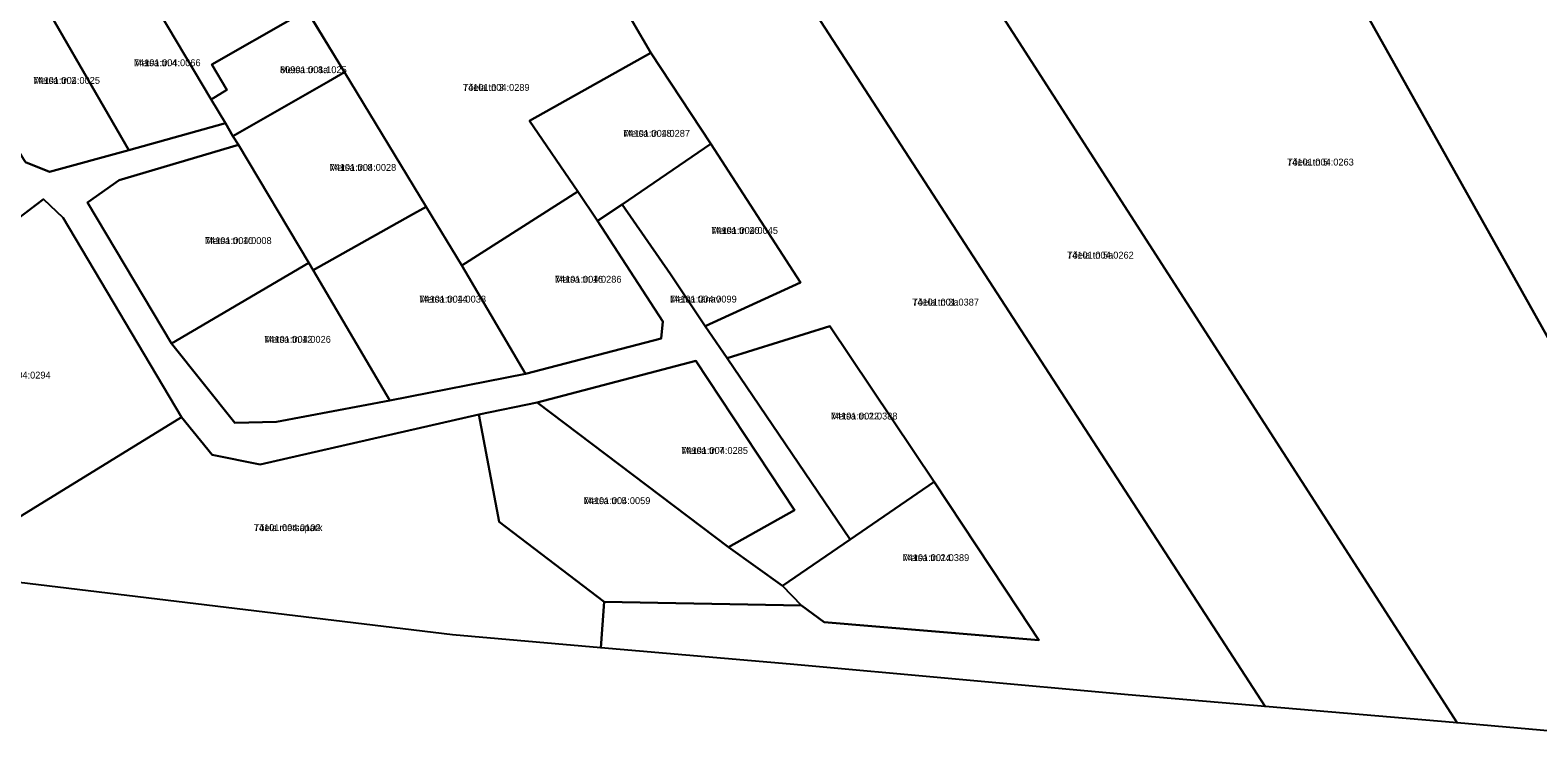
# Model space of a CAD drawing. Extents: x 524000 to 564260, y 6469338 to 6496391.
# Drawn here: x 537928.9 to 538256.7, y 6472778 to 6472932.3 of the extents above; entities that cross this region are included whole.
import ezdxf

# ---------------------------------------------------------------- set-up
doc = ezdxf.new("R2010")
doc.units = 0
for name, color, linetype in [('L_AADRESS', 7, 'Continuous'), ('PIIR', 7, 'Continuous'), ('TUNNUS', 7, 'Continuous')]:
    doc.layers.add(name, color=color, linetype=linetype)

msp = doc.modelspace()

# ---------------------------------------------------------------- linework, layer by layer
at = {"layer": 'PIIR'}
for points in [[(538254.62, 6473081.05), (538407.66, 6472852.49), (538381.66, 6472835.41), (538374.77, 6472836.59), (538368.09, 6472824.25), (538395.14, 6472779.98), (538307.73, 6472778.3), (538204.69, 6472962.04), (538224, 6472975.7), (538226.87, 6472970.76), (538255.54, 6472991.23), (538216.33, 6473054.12)], [(538156.34, 6473048.5), (538204.69, 6472962.04), (538307.73, 6472778.3), (538280.97, 6472777.95), (538239.16, 6472781.62), (538096.61, 6473003.26)], [(538096.61, 6473003.26), (538239.16, 6472781.62), (538197.42, 6472785.22), (538069.5, 6472982.51)], [(538063.82, 6472927.37), (538043.92, 6472961.49), (538069.5, 6472982.51), (538197.42, 6472785.22), (538167.63, 6472787.73), (538094.14, 6472794.44), (538052.97, 6472797.96), (538053.69, 6472807.94), (538096.61, 6472807.14), (538101.49, 6472803.54), (538148.19, 6472799.6), (538143.82, 6472806.23), (538125.46, 6472834.03), (538102.73, 6472867.87), (538080.43, 6472860.92), (538075.66, 6472867.92), (538096.35, 6472877.38), (538076.89, 6472907.52)], [(538022.72, 6472881.08), (538014.96, 6472893.88), (537997.23, 6472923.11), (537982.1, 6472947.96), (538043.92, 6472961.49), (538063.82, 6472927.37), (538037.41, 6472912.57), (538047.97, 6472897.18)], [(537968.23, 6472917.21), (537953.06, 6472942.7), (537977.91, 6472947.2), (537982.1, 6472947.96), (537989.01, 6472936.61), (537986.38, 6472935.11), (537968.34, 6472924.82), (537971.65, 6472919.27)], [(537950.29, 6472906.18), (537931.53, 6472938.68), (537953.06, 6472942.7), (537968.23, 6472917.21), (537971.31, 6472912.04)], [(537927.85, 6472903.53), (537908.79, 6472934.6), (537931.53, 6472938.68), (537950.29, 6472906.18), (537933.05, 6472901.44)], [(537993.74, 6472921.12), (537972.96, 6472909.24), (537971.31, 6472912.04), (537968.23, 6472917.21), (537971.65, 6472919.27), (537968.34, 6472924.82), (537986.38, 6472935.11), (537989.01, 6472936.61), (537997.23, 6472923.11)], [(538047.97, 6472897.18), (538037.41, 6472912.57), (538063.82, 6472927.37), (538076.89, 6472907.52), (538057.56, 6472894.38), (538052.2, 6472890.78)], [(537974.18, 6472907.34), (537972.96, 6472909.24), (537993.74, 6472921.12), (537997.23, 6472923.11), (538014.96, 6472893.88), (538011.59, 6472891.99), (537990.39, 6472880.11), (537989.46, 6472881.7)], [(538076.89, 6472907.52), (538096.35, 6472877.38), (538075.66, 6472867.92), (538068.11, 6472879.2), (538057.56, 6472894.38)], [(537948.25, 6472899.66), (537974.18, 6472907.34), (537989.46, 6472881.7), (537959.58, 6472864.17), (537941.31, 6472894.78)], [(537911.94, 6472817.51), (537880.7, 6472856.63), (537881.69, 6472857.39), (537931.73, 6472895.5), (537936.05, 6472891.43), (537961.8, 6472848.15), (537913.82, 6472818.62)], [(538022.72, 6472881.08), (538047.97, 6472897.18), (538052.2, 6472890.78), (538066.45, 6472868.92), (538066.08, 6472865.25), (538036.57, 6472857.51)], [(537990.39, 6472880.11), (538011.59, 6472891.99), (538014.96, 6472893.88), (538022.72, 6472881.08), (538036.57, 6472857.51), (538007.05, 6472851.75)], [(537973.36, 6472846.89), (537959.58, 6472864.17), (537989.46, 6472881.7), (537990.39, 6472880.11), (538007.05, 6472851.75), (537982.46, 6472847.11)], [(538125.46, 6472834.03), (538107.13, 6472821.5), (538080.43, 6472860.92), (538102.73, 6472867.87)], [(538073.6, 6472860.39), (538095.07, 6472827.89), (538080.71, 6472819.87), (538039.14, 6472851.29)], [(537911.94, 6472817.51), (537913.82, 6472818.62), (537961.8, 6472848.15), (537968.46, 6472839.9), (537978.87, 6472837.81), (538026.41, 6472848.72), (538030.81, 6472825.39), (538053.69, 6472807.94), (538052.97, 6472797.96), (538020.71, 6472800.82), (537915.62, 6472813.49)], [(538026.41, 6472848.72), (538039.14, 6472851.29), (538080.71, 6472819.87), (538092.46, 6472811.47), (538096.61, 6472807.14), (538053.69, 6472807.94), (538030.81, 6472825.39)], [(538096.61, 6472807.14), (538092.46, 6472811.47), (538107.13, 6472821.5), (538125.46, 6472834.03), (538143.82, 6472806.23), (538148.19, 6472799.6), (538101.49, 6472803.54)]]:
    msp.add_lwpolyline(points, close=True, dxfattribs=at)
msp.add_lwpolyline([(537927.85, 6472903.53), (537933.05, 6472901.44), (537950.29, 6472906.18), (537971.31, 6472912.04), (537972.96, 6472909.24), (537974.18, 6472907.34), (537948.25, 6472899.66), (537941.31, 6472894.78), (537959.58, 6472864.17), (537973.36, 6472846.89), (537982.46, 6472847.11), (538007.05, 6472851.75), (538036.57, 6472857.51), (538066.08, 6472865.25), (538066.45, 6472868.92), (538052.2, 6472890.78), (538057.56, 6472894.38), (538068.11, 6472879.2), (538075.66, 6472867.92), (538080.43, 6472860.92), (538107.13, 6472821.5), (538092.46, 6472811.47), (538080.71, 6472819.87), (538095.07, 6472827.89), (538073.6, 6472860.39), (538039.14, 6472851.29), (538026.41, 6472848.72), (537978.87, 6472837.81), (537968.46, 6472839.9), (537961.8, 6472848.15), (537936.05, 6472891.43), (537931.73, 6472895.5), (537926.07, 6472891.19)], dxfattribs=at)

# ---------------------------------------------------------------- texts
at = {"layer": 'L_AADRESS'}
for s, p in [('Metsa tn 4', (537951.42, 6472924.44)), ('Metsa tn 8a', (537983.19, 6472922.92)), ('Metsa tn 2', (537929.54, 6472920.59)), ('Tõela tn 3', (538022.96, 6472919.07)), ('Metsa tn 18', (538057.84, 6472909.08)), ('Tõela tn 5', (538202.17, 6472902.84)), ('Metsa tn 8', (537993.96, 6472901.68)), ('Metsa tn 20', (538076.96, 6472887.97)), ('Metsa tn 10', (537966.87, 6472885.76)), ('Tõela tn 5a', (538154.33, 6472882.6)), ('Metsa tn 16', (538042.94, 6472877.35)), ('Metsa tn 14', (538013.48, 6472873.03)), ('Metsa tänav', (538068, 6472873.04)), ('Tõela tn 3a', (538120.67, 6472872.38)), ('Metsa tn 12', (537979.74, 6472864.29)), ('Metsa tn 22', (538102.95, 6472847.61)), ('Metsa tn 7', (538070.44, 6472840.13)), ('Metsa tn 5', (538049.22, 6472829.21)), ('Tõela metsapark', (537977.49, 6472823.34)), ('Metsa tn 24', (538118.55, 6472816.82))]:
    msp.add_text(s, height=1.5, dxfattribs=at).set_placement(p)
at = {"layer": 'TUNNUS'}
for s, p in [('74101:004:0066', (537951.42, 6472924.44)), ('80901:001:1025', (537983.19, 6472922.92)), ('74101:004:0025', (537929.54, 6472920.59)), ('74101:004:0289', (538022.96, 6472919.07)), ('74101:004:0287', (538057.84, 6472909.08)), ('74101:004:0263', (538202.17, 6472902.84)), ('74101:004:0028', (537993.96, 6472901.68)), ('74101:004:0045', (538076.96, 6472887.97)), ('74101:004:0008', (537966.87, 6472885.76)), ('74101:004:0262', (538154.33, 6472882.6)), ('74101:004:0286', (538042.94, 6472877.35)), ('74101:004:0038', (538013.48, 6472873.03)), ('74101:004:0099', (538068, 6472873.04)), ('74101:001:0387', (538120.67, 6472872.38)), ('74101:004:0026', (537979.74, 6472864.29)), ('74101:004:0294', (537918.81, 6472856.51)), ('74101:001:0388', (538102.95, 6472847.61)), ('74101:004:0285', (538070.44, 6472840.13)), ('74101:004:0059', (538049.22, 6472829.21)), ('74101:004:0102', (537977.49, 6472823.34)), ('74101:001:0389', (538118.55, 6472816.82))]:
    msp.add_text(s, height=1.5, dxfattribs=at).set_placement(p)

doc.saveas('drawing.dxf')
